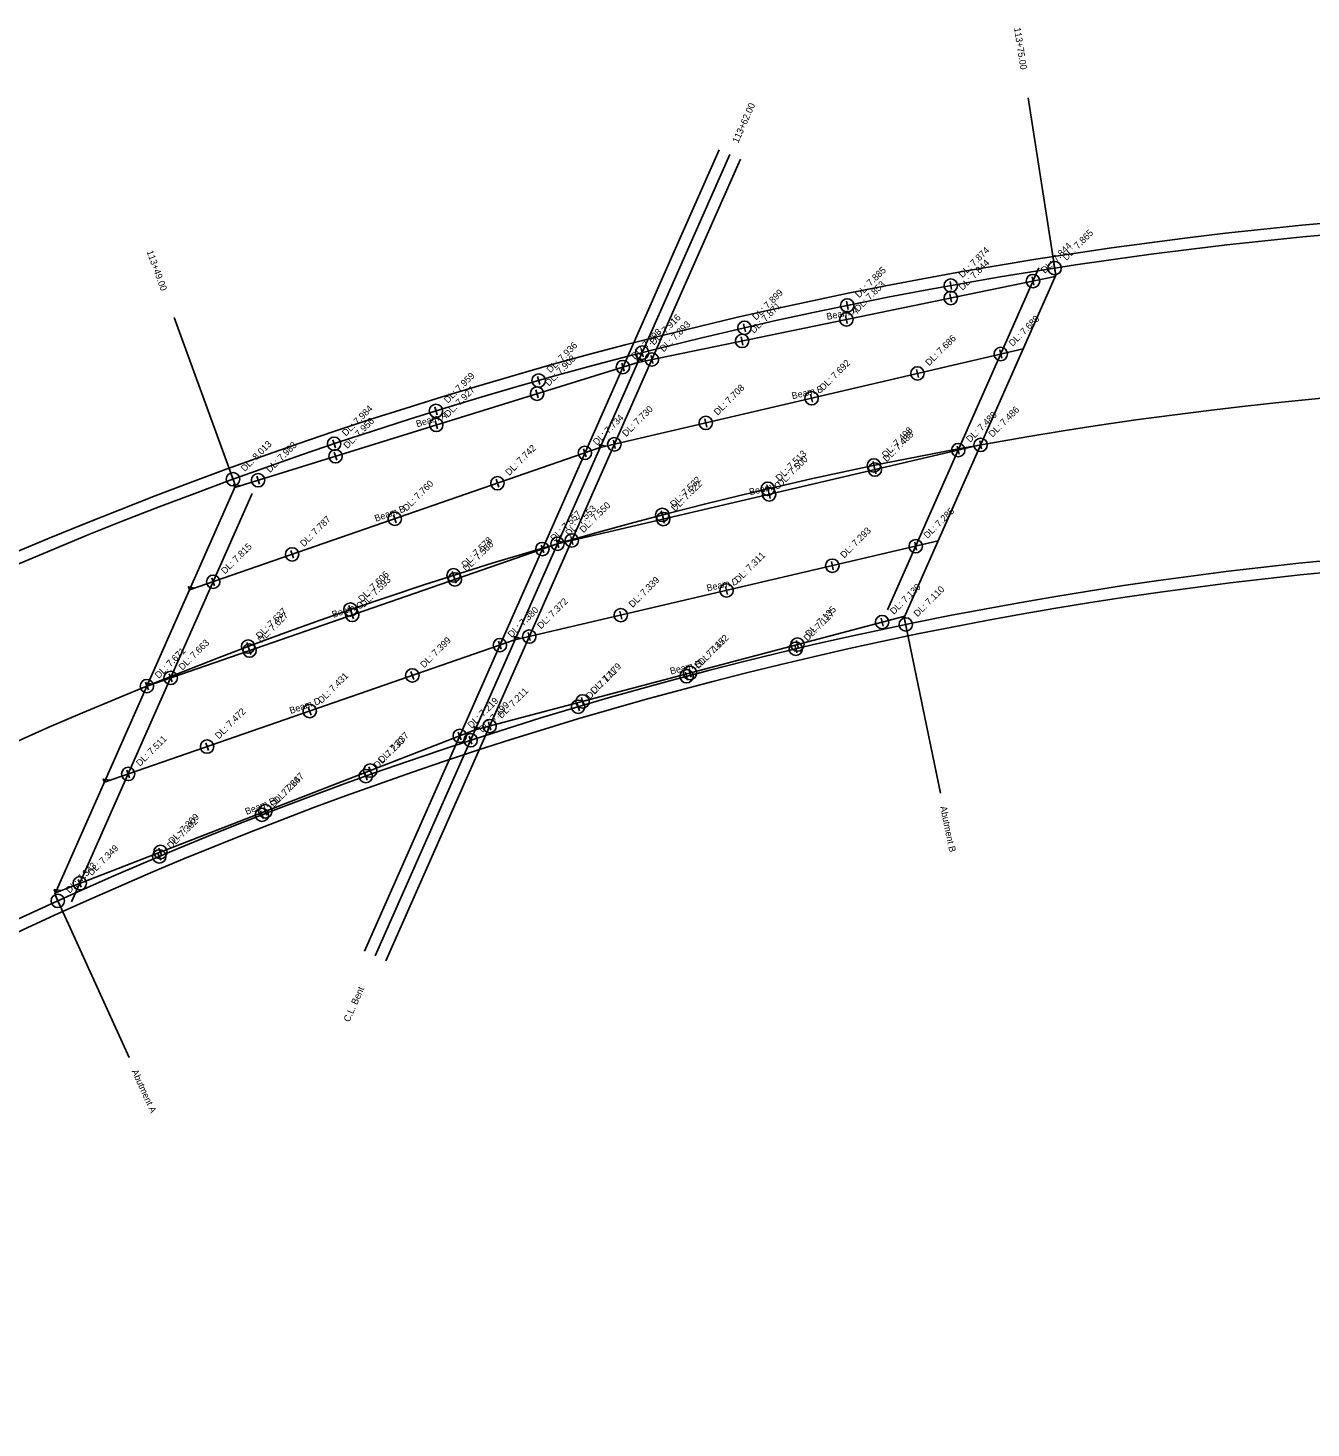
# Model space of a CAD drawing. Extents: x 99615 to 99752, y 50258 to 50300.
# Drawn here: x 99645.22 to 99683.58, y 50257.72 to 50299.59 of the extents above; entities that cross this region are included whole.
import ezdxf

# ---------------------------------------------------------------- set-up
doc = ezdxf.new("R2010")
doc.units = 0
for name, color, linetype in [('Level 1', 7, 'Continuous'), ('Level 10', 7, 'Continuous'), ('Level 21', 7, 'Continuous'), ('Level 23', 7, 'Continuous')]:
    doc.layers.add(name, color=color, linetype=linetype)

msp = doc.modelspace()

# ---------------------------------------------------------------- linework, layer by layer
at = {"layer": 'Level 1'}
for p, q in [((99665.879, 50295.951), (99655.276, 50271.98)), ((99666.519, 50295.668), (99655.916, 50271.697)), ((99675.444, 50292.422), (99670.916, 50282.187)), ((99651.922, 50285.674), (99646.52, 50273.46))]:
    msp.add_line(p, q, dxfattribs=at)
for points in [[(99663.449, 50289.592), (99675.93, 50292.162)], [(99662.321, 50287.042), (99674.974, 50290.001)], [(99651.4, 50285.852), (99663.449, 50289.592)], [(99663.618, 50289.627), (99663.429, 50289.69), (99663.449, 50289.592)], [(99650.044, 50282.786), (99662.321, 50287.042)], [(99661.049, 50284.167), (99673.702, 50287.126)], [(99662.49, 50287.082), (99662.298, 50287.14), (99662.321, 50287.042)], [(99651.565, 50285.903), (99651.37, 50285.947), (99651.4, 50285.852)], [(99648.772, 50279.911), (99661.049, 50284.167)], [(99659.778, 50281.292), (99672.431, 50284.251)], [(99661.218, 50284.207), (99661.027, 50284.264), (99661.049, 50284.167)], [(99650.207, 50282.843), (99650.011, 50282.881), (99650.044, 50282.786)], [(99658.587, 50278.6), (99671.437, 50282.004)], [(99647.5, 50277.036), (99659.778, 50281.292)], [(99659.946, 50281.332), (99659.755, 50281.389), (99659.778, 50281.292)], [(99648.936, 50279.968), (99648.739, 50280.006), (99648.772, 50279.911)], [(99646.038, 50273.731), (99658.587, 50278.6)], [(99658.754, 50278.644), (99658.561, 50278.696), (99658.587, 50278.6)], [(99647.664, 50277.093), (99647.468, 50277.131), (99647.5, 50277.036)], [(99646.2, 50273.793), (99646.002, 50273.824), (99646.038, 50273.731)]]:
    msp.add_lwpolyline(points, dxfattribs=at)
at = {"layer": 'Level 10'}
for p, q in [((99675.895, 50292.536), (99675.933, 50292.289)), ((99672.786, 50292.016), (99672.83, 50291.769)), ((99675.294, 50291.903), (99675.243, 50292.148)), ((99672.835, 50291.397), (99672.784, 50291.642)), ((99669.69, 50291.42), (99669.74, 50291.175)), ((99666.61, 50290.749), (99666.666, 50290.506)), ((99669.715, 50290.754), (99669.664, 50290.999)), ((99666.594, 50290.112), (99666.544, 50290.357)), ((99663.547, 50290.004), (99663.609, 50289.762)), ((99663.547, 50290.004), (99663.609, 50289.762)), ((99663.895, 50289.556), (99663.845, 50289.801)), ((99674.332, 50289.722), (99674.275, 50289.965)), ((99663.042, 50289.335), (99662.968, 50289.574)), ((99671.839, 50289.139), (99671.782, 50289.383)), ((99660.452, 50289.171), (99660.52, 50288.93)), ((99660.474, 50288.537), (99660.4, 50288.776)), ((99668.676, 50288.4), (99668.619, 50288.643)), ((99657.378, 50288.261), (99657.452, 50288.022)), ((99657.461, 50287.602), (99657.387, 50287.841)), ((99665.513, 50287.66), (99665.456, 50287.903)), ((99654.328, 50287.276), (99654.408, 50287.039)), ((99662.776, 50287.02), (99662.719, 50287.264)), ((99654.449, 50286.668), (99654.375, 50286.906)), ((99661.91, 50286.767), (99661.828, 50287.004)), ((99673.06, 50286.847), (99673.003, 50287.09)), ((99673.68, 50287.249), (99673.724, 50287.003)), ((99670.486, 50286.632), (99670.537, 50286.387)), ((99670.568, 50286.264), (99670.511, 50286.508)), ((99651.303, 50286.216), (99651.389, 50285.981)), ((99652.134, 50285.949), (99652.06, 50286.188)), ((99659.293, 50285.86), (99659.211, 50286.096)), ((99667.309, 50285.933), (99667.366, 50285.689)), ((99667.404, 50285.525), (99667.347, 50285.768)), ((99656.223, 50284.796), (99656.141, 50285.032)), ((99664.151, 50285.151), (99664.214, 50284.909)), ((99664.241, 50284.785), (99664.184, 50285.028)), ((99661.505, 50284.145), (99661.448, 50284.389)), ((99653.154, 50283.732), (99653.072, 50283.968)), ((99660.638, 50283.892), (99660.556, 50284.129)), ((99661.015, 50284.287), (99661.084, 50284.047)), ((99661.015, 50284.287), (99661.084, 50284.047)), ((99671.788, 50283.972), (99671.731, 50284.215)), ((99669.296, 50283.389), (99669.239, 50283.633)), ((99650.795, 50282.914), (99650.713, 50283.151)), ((99657.902, 50283.342), (99657.977, 50283.104)), ((99658.021, 50282.985), (99657.939, 50283.221)), ((99666.133, 50282.65), (99666.076, 50282.893)), ((99654.814, 50282.317), (99654.896, 50282.081)), ((99654.952, 50281.921), (99654.87, 50282.157)), ((99662.969, 50281.91), (99662.913, 50282.153)), ((99670.788, 50281.702), (99670.724, 50281.944)), ((99671.438, 50281.876), (99671.488, 50281.631)), ((99660.233, 50281.27), (99660.176, 50281.514)), ((99651.755, 50281.212), (99651.843, 50280.977)), ((99651.882, 50280.857), (99651.8, 50281.093)), ((99659.367, 50281.017), (99659.285, 50281.253)), ((99668.146, 50281.147), (99668.204, 50280.904)), ((99668.256, 50281.032), (99668.192, 50281.273)), ((99649.523, 50280.039), (99649.441, 50280.275)), ((99656.749, 50280.11), (99656.667, 50280.346)), ((99664.876, 50280.326), (99664.941, 50280.085)), ((99665.044, 50280.181), (99664.98, 50280.422)), ((99648.725, 50280.027), (99648.819, 50279.795)), ((99661.631, 50279.414), (99661.702, 50279.174)), ((99661.831, 50279.33), (99661.767, 50279.571)), ((99653.68, 50279.046), (99653.598, 50279.282)), ((99658.17, 50278.304), (99658.08, 50278.537)), ((99659.052, 50278.594), (99658.988, 50278.835)), ((99650.611, 50277.982), (99650.529, 50278.218)), ((99658.412, 50278.411), (99658.49, 50278.173)), ((99658.412, 50278.411), (99658.49, 50278.173)), ((99648.252, 50277.164), (99648.17, 50277.4)), ((99655.274, 50277.337), (99655.358, 50277.101)), ((99655.495, 50277.266), (99655.404, 50277.499)), ((99652.167, 50276.176), (99652.258, 50275.943)), ((99652.358, 50276.049), (99652.267, 50276.282)), ((99649.093, 50274.931), (99649.19, 50274.7)), ((99649.221, 50274.831), (99649.13, 50275.064)), ((99646.81, 50273.896), (99646.719, 50274.129)), ((99646.054, 50273.601), (99646.158, 50273.373))]:
    msp.add_line(p, q, dxfattribs=at)
for centre in [(99675.914, 50292.412), (99672.808, 50291.892), (99675.268, 50292.026), (99669.715, 50291.297), (99672.81, 50291.519), (99669.689, 50290.877), (99666.638, 50290.627), (99666.569, 50290.234), (99663.578, 50289.883), (99663.578, 50289.883), (99663.87, 50289.679), (99674.303, 50289.844), (99663.005, 50289.454), (99671.811, 50289.261), (99660.486, 50289.05), (99660.437, 50288.657), (99668.648, 50288.521), (99657.415, 50288.142), (99657.424, 50287.722), (99665.484, 50287.782), (99654.368, 50287.157), (99662.748, 50287.142), (99673.702, 50287.126), (99654.412, 50286.787), (99661.869, 50286.886), (99673.032, 50286.969), (99670.511, 50286.51), (99670.539, 50286.386), (99651.346, 50286.098), (99652.097, 50286.068), (99659.252, 50285.978), (99667.337, 50285.811), (99667.376, 50285.646), (99664.183, 50285.03), (99656.182, 50284.914), (99664.213, 50284.907), (99661.049, 50284.167), (99661.049, 50284.167), (99661.476, 50284.267), (99653.113, 50283.85), (99660.597, 50284.01), (99671.76, 50284.094), (99669.267, 50283.511), (99650.754, 50283.032), (99657.94, 50283.223), (99657.98, 50283.103), (99666.104, 50282.771), (99654.855, 50282.199), (99654.911, 50282.039), (99662.941, 50282.032), (99670.756, 50281.823), (99671.463, 50281.754), (99660.205, 50281.392), (99651.799, 50281.094), (99651.841, 50280.975), (99659.326, 50281.135), (99668.175, 50281.026), (99668.224, 50281.153), (99649.482, 50280.157), (99656.708, 50280.228), (99664.908, 50280.205), (99665.012, 50280.302), (99648.772, 50279.911), (99653.639, 50279.164), (99661.666, 50279.294), (99661.799, 50279.451), (99659.02, 50278.714), (99658.125, 50278.42), (99658.451, 50278.292), (99658.451, 50278.292), (99650.57, 50278.1), (99648.211, 50277.282), (99655.316, 50277.219), (99655.45, 50277.382), (99652.212, 50276.06), (99652.313, 50276.165), (99649.175, 50274.948), (99649.141, 50274.815), (99646.764, 50274.012), (99646.106, 50273.487)]:
    msp.add_circle(centre, 0.2, dxfattribs=at)
at = {"layer": 'Level 23'}
for p, q in [((99666.199, 50295.809), (99655.596, 50271.838)), ((99675.947, 50292.2), (99671.419, 50281.964)), ((99651.419, 50285.896), (99646.017, 50273.683))]:
    msp.add_line(p, q, dxfattribs=at)
for points in [[(99675.947, 50292.2), (99675.125, 50297.502)], [(99651.419, 50285.896), (99649.583, 50290.937)], [(99671.419, 50281.964), (99672.506, 50276.711)], [(99646.017, 50273.683), (99648.236, 50268.798)]]:
    msp.add_lwpolyline(points, dxfattribs=at)
for radius, start, end in [(130.2, 64.4283, 96.51394), (130.2, 64.4283, 96.51394), (130.2, 64.4283, 96.51394), (129.85, 64.4283, 96.51394), (129.85, 64.4283, 96.51394), (129.85, 64.4283, 96.51394), (130.2, 96.51394, 128.59957), (130.2, 96.51394, 128.59957), (130.2, 96.51394, 128.59957), (129.85, 96.51394, 128.59957), (129.85, 96.51394, 128.59957), (129.85, 96.51394, 128.59957), (125, 64.4283, 96.51394), (125, 64.4283, 96.51394), (125, 64.4283, 96.51394), (125, 96.51394, 128.59957), (125, 96.51394, 128.59957), (125, 96.51394, 128.59957), (120.15, 64.4283, 96.51394), (120.15, 64.4283, 96.51394), (120.15, 64.4283, 96.51394), (119.8, 64.4283, 96.51394), (119.8, 64.4283, 96.51394), (119.8, 64.4283, 96.51394), (120.15, 96.51394, 128.59957), (120.15, 96.51394, 128.59957), (120.15, 96.51394, 128.59957), (119.8, 96.51394, 128.59957), (119.8, 96.51394, 128.59957), (119.8, 96.51394, 128.59957)]:
    msp.add_arc((99695.797, 50164.094), radius, start, end, dxfattribs=at)

# ---------------------------------------------------------------- texts
at = {"layer": 'Level 1'}
for s, rotation, p in [('Beam A', 11.6358, (99669.114, 50290.861)), ('Beam B', 13.1602, (99668.077, 50288.491)), ('Beam A', 17.2437, (99656.853, 50287.649)), ('Beam C', 13.1602, (99666.805, 50285.616)), ('Beam B', 19.119, (99655.618, 50284.824)), ('Beam D', 13.1602, (99665.533, 50282.74)), ('Beam C', 19.119, (99654.346, 50281.949)), ('Beam E', 14.8376, (99664.442, 50280.254)), ('Beam D', 19.119, (99653.074, 50279.074)), ('Beam E', 21.2065, (99651.752, 50276.055))]:
    msp.add_text(s, height=0.2, rotation=rotation, dxfattribs=at).set_placement(p)
at = {"layer": 'Level 10'}
for s, p in [('DL: 7.865', (99676.267, 50292.625)), ('DL: 7.844', (99675.622, 50292.238)), ('DL: 7.874', (99673.161, 50292.105)), ('DL: 7.885', (99670.069, 50291.51)), ('DL: 7.844', (99673.163, 50291.732)), ('DL: 7.853', (99670.043, 50291.089)), ('DL: 7.899', (99666.991, 50290.84)), ('DL: 7.916', (99663.931, 50290.095)), ('DL: 7.916', (99663.931, 50290.095)), ('DL: 7.871', (99666.923, 50290.446)), ('DL: 7.893', (99664.223, 50289.891)), ('DL: 7.688', (99674.657, 50290.056)), ('DL: 7.936', (99660.839, 50289.262)), ('DL: 7.898', (99663.359, 50289.666)), ('DL: 7.686', (99672.164, 50289.473)), ('DL: 7.908', (99660.79, 50288.869)), ('DL: 7.692', (99669.001, 50288.734)), ('DL: 7.959', (99657.769, 50288.354)), ('DL: 7.927', (99657.778, 50287.934)), ('DL: 7.708', (99665.838, 50287.994)), ('DL: 7.984', (99654.721, 50287.37)), ('DL: 7.730', (99663.101, 50287.354)), ('DL: 7.488', (99673.385, 50287.181)), ('DL: 7.486', (99674.056, 50287.338)), ('DL: 7.956', (99654.766, 50286.999)), ('DL: 7.734', (99662.223, 50287.098)), ('DL: 7.498', (99670.865, 50286.722)), ('DL: 7.488', (99670.893, 50286.598)), ('DL: 8.013', (99651.699, 50286.31)), ('DL: 7.983', (99652.45, 50286.28)), ('DL: 7.742', (99659.605, 50286.19)), ('DL: 7.513', (99667.691, 50286.023)), ('DL: 7.500', (99667.729, 50285.858)), ('DL: 7.760', (99656.536, 50285.126)), ('DL: 7.532', (99664.536, 50285.242)), ('DL: 7.522', (99664.566, 50285.119)), ('DL: 7.557', (99660.951, 50284.223)), ('DL: 7.553', (99661.403, 50284.379)), ('DL: 7.553', (99661.403, 50284.379)), ('DL: 7.550', (99661.83, 50284.479)), ('DL: 7.285', (99672.113, 50284.306)), ('DL: 7.787', (99653.467, 50284.062)), ('DL: 7.578', (99658.293, 50283.435)), ('DL: 7.293', (99669.621, 50283.723)), ('DL: 7.815', (99651.108, 50283.245)), ('DL: 7.568', (99658.334, 50283.315)), ('DL: 7.311', (99666.458, 50282.983)), ('DL: 7.606', (99655.209, 50282.411)), ('DL: 7.593', (99655.264, 50282.251)), ('DL: 7.339', (99663.295, 50282.244)), ('DL: 7.130', (99671.109, 50282.035)), ('DL: 7.110', (99671.817, 50281.966)), ('DL: 7.637', (99652.152, 50281.307)), ('DL: 7.380', (99659.679, 50281.347)), ('DL: 7.372', (99660.558, 50281.604)), ('DL: 7.135', (99668.578, 50281.365)), ('DL: 7.627', (99652.195, 50281.187)), ('DL: 7.127', (99668.528, 50281.238)), ('DL: 7.152', (99665.365, 50280.514)), ('DL: 7.671', (99649.126, 50280.123)), ('DL: 7.663', (99649.836, 50280.369)), ('DL: 7.399', (99657.062, 50280.44)), ('DL: 7.147', (99665.262, 50280.418)), ('DL: 7.179', (99662.153, 50279.663)), ('DL: 7.431', (99653.993, 50279.376)), ('DL: 7.171', (99662.02, 50279.506)), ('DL: 7.211', (99659.374, 50278.926)), ('DL: 7.219', (99658.478, 50278.632)), ('DL: 7.199', (99658.804, 50278.504)), ('DL: 7.199', (99658.804, 50278.504)), ('DL: 7.472', (99650.923, 50278.312)), ('DL: 7.237', (99655.803, 50277.594)), ('DL: 7.511', (99648.564, 50277.494)), ('DL: 7.230', (99655.67, 50277.431)), ('DL: 7.264', (99652.566, 50276.272)), ('DL: 7.267', (99652.666, 50276.377)), ('DL: 7.302', (99649.495, 50275.028)), ('DL: 7.309', (99649.529, 50275.16)), ('DL: 7.349', (99647.118, 50274.224)), ('DL: 7.343', (99646.46, 50273.699))]:
    msp.add_text(s, height=0.2, rotation=45, dxfattribs=at).set_placement(p)
at = {"layer": 'Level 21'}
for s, rotation, p in [('113+75.00', 278.8079, (99674.7, 50299.594)), ('113+62.00', 66.1396, (99666.452, 50296.135)), ('113+49.00', 290.0187, (99648.759, 50292.907)), ('Abutment B', 281.6849, (99672.489, 50276.299)), ('C.L. Bent', 66.1396, (99654.824, 50269.846)), ('Abutment A', 294.4295, (99648.31, 50268.392))]:
    msp.add_text(s, height=0.2, rotation=rotation, dxfattribs=at).set_placement(p)

doc.saveas('drawing.dxf')
